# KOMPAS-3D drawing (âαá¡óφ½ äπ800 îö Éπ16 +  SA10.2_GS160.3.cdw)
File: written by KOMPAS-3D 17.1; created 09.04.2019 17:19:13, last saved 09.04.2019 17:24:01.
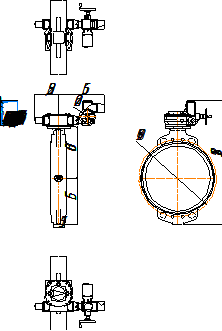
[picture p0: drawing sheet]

Sheet 1: A4, portrait

Title block, sheet 1: name: Гранвэл Ду800 МФ Ру16 + / SA10.2_GS160.3; material: Внимание! Данный продукт является объектом авторского права ООО «Торговый Дом АДЛ». / Запрещается изменение, копирование, распространение / (в том числе путем копирования на другие сайты и ресурсы в Интернете) / или любое иное использование информации и объектов без предварительного / согласия правообладателя (ООО «Торговый Дом АДЛ»).; mass: 523; sheets: 1; organisation: ООО "Торговый дом АДЛ"; sheet format: A4

Views: Вид 1, Проекционный вид 2, Проекционный вид 3, Проекционный вид 4
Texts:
  user
Dimensions and other numbers on the sheet: 630; 565; 135; 289,5; 200; 950; 1517,8; 1:1; 1; 523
